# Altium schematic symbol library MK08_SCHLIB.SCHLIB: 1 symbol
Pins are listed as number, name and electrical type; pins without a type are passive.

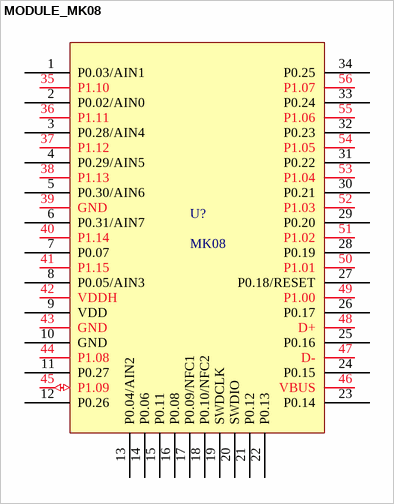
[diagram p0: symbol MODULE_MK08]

## MODULE_MK08
designator U?, comment MK08
footprint PCB_MK08 (21*13.8mm)
pins: 1 P0.03/AIN1, 2 P0.02/AIN0, 3 P0.28/AIN4, 4 P0.29/AIN5, 5 P0.30/AIN6, 6 P0.31/AIN7, 7 P0.07, 8 P0.05/AIN3, 9 VDD, 10 GND, 11 P0.27, 12 P0.26, 13 P0.04/AIN2, 14 P0.06, 15 P0.11, 16 P0.08, 17 P0.09/NFC1, 18 P0.10/NFC2, 19 SWDCLK, 20 SWDIO, 21 P0.12, 22 P0.13, 23 P0.14, 24 P0.15, 25 P0.16, 26 P0.17, 27 P0.18/RESET, 28 P0.19, 29 P0.20, 30 P0.21, 31 P0.22, 32 P0.23, 33 P0.24, 34 P0.25, 35 P1.10, 36 P1.11, 37 P1.12, 38 P1.13, 39 GND, 40 P1.14, 41 P1.15, 42 VDDH, 43 GND, 44 P1.08, 45 P1.09 (io), 46 VBUS, 47 D-, 48  D+, 49  P1.00, 50 P1.01, 51 P1.02, 52 P1.03, 53 P1.04, 54  P1.05, 55 P1.06, 56 P1.07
